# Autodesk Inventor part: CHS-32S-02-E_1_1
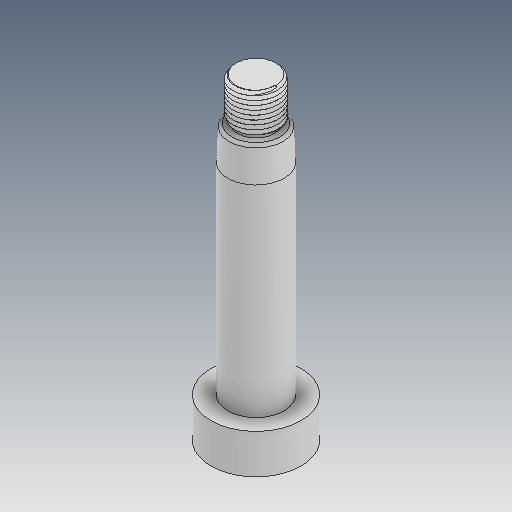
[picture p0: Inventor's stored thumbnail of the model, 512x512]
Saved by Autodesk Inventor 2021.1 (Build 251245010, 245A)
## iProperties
Created: 2021-05
Part Number: CHS-32S-02-E_1_1
Material: Ogólny
Document SubType Name: Modeling
Designer: user
Density: 1 g/cm^3
Appearance: Domyślna
Author: user
Revision Number: ÈÎºÎ
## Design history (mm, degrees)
feature "ÊäÈë1"
feature "ÊäÈë2"
node "Bryła1"
node "Bryła2"
